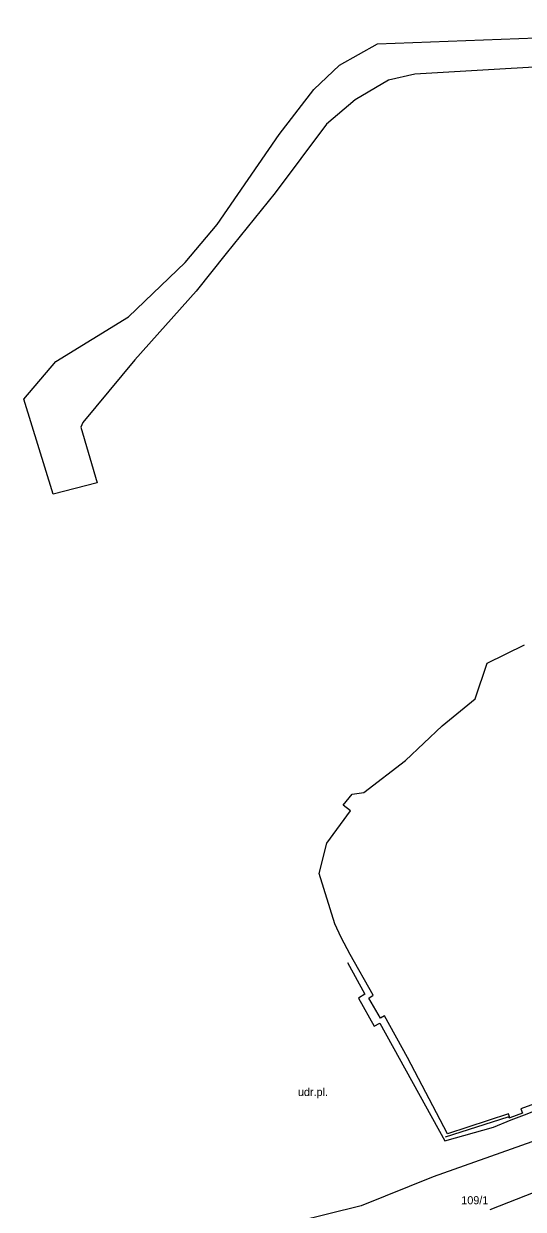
# Model space of a CAD drawing. Extents: x -836568 to -836015, y -1070547 to -1070212.
# Drawn here: x -836568.3 to -836522, y -1070322.1 to -1070212.1 of the extents above; entities that cross this region are included whole.
import ezdxf

# ---------------------------------------------------------------- set-up
doc = ezdxf.new("R2010")
doc.units = 0
for name, color, linetype in [('BodPole_mer', 7, 'Continuous'), ('Doprava_hranice', 7, 'Continuous'), ('OstPloch_hranice', 7, 'Continuous'), ('RuianPar_popis', 7, 'Continuous'), ('Stavby_linie', 7, 'Continuous'), ('Vodstvo_hranice', 7, 'Continuous'), ('Zelen_kody', 7, 'Continuous')]:
    doc.layers.add(name, color=color, linetype=linetype)

msp = doc.modelspace()

# ---------------------------------------------------------------- linework, layer by layer
at = {"layer": 'BodPole_mer'}
for p, q in [((-836536.32, -1070302.47), (-836536.32, -1070302.47)), ((-836535.91, -1070302.21), (-836535.91, -1070302.21)), ((-836534.86, -1070304.13), (-836534.86, -1070304.13)), ((-836535.82, -1070305.08), (-836535.82, -1070305.08)), ((-836535.28, -1070304.8), (-836535.28, -1070304.8)), ((-836535.22, -1070304.34), (-836535.22, -1070304.34)), ((-836532.73, -1070307.98), (-836532.73, -1070307.98)), ((-836522.22, -1070312.76), (-836522.22, -1070312.76)), ((-836523.38, -1070313.48), (-836523.38, -1070313.48)), ((-836523.35, -1070313.2), (-836523.35, -1070313.2)), ((-836523.23, -1070313.58), (-836523.23, -1070313.58)), ((-836523.12, -1070313.78), (-836523.12, -1070313.78)), ((-836522.07, -1070313.16), (-836522.07, -1070313.16)), ((-836529.02, -1070315.07), (-836529.02, -1070315.07)), ((-836524.75, -1070314.46), (-836524.75, -1070314.46)), ((-836529.27, -1070315.73), (-836529.27, -1070315.73)), ((-836529.2, -1070315.35), (-836529.2, -1070315.35)), ((-836530.36, -1070319.04), (-836530.36, -1070319.04)), ((-836537.03, -1070321.73), (-836537.03, -1070321.73))]:
    msp.add_line(p, q, dxfattribs=at)
at = {"layer": 'Doprava_hranice'}
for points in [[(-836565.55, -1070255.75), (-836568.29, -1070246.94), (-836565.3, -1070243.45), (-836558.59, -1070239.29), (-836553.32, -1070234.26), (-836550.36, -1070230.73), (-836544.63, -1070222.38), (-836541.42, -1070218.21), (-836539.02, -1070215.95), (-836535.5, -1070213.99), (-836517.48, -1070213.29), (-836497.22, -1070212.11), (-836494.05, -1070212.5), (-836489.39, -1070214.02), (-836485.93, -1070216.36), (-836482.28, -1070220.4), (-836478.23, -1070227.56), (-836471.79, -1070243.33), (-836465.92, -1070256.62), (-836463.85, -1070260.25), (-836463.13, -1070260.78)], [(-836466.54, -1070263.19), (-836474.56, -1070243.73), (-836478.12, -1070235.21), (-836483.33, -1070224.14), (-836486.58, -1070219.75), (-836489.27, -1070217.57), (-836492.22, -1070215.97), (-836495.08, -1070215.2), (-836498.82, -1070214.84), (-836513.64, -1070215.7), (-836532.05, -1070216.8), (-836534.5, -1070217.36), (-836537.57, -1070219.18), (-836540.24, -1070221.43), (-836545, -1070227.8), (-836549.52, -1070233.43), (-836552.32, -1070236.92), (-836557.98, -1070243.27), (-836562.8, -1070249.08), (-836563.01, -1070249.54), (-836561.48, -1070254.69), (-836565.55, -1070255.75)], [(-836486.39, -1070290.44), (-836494.37, -1070298.76), (-836499.1, -1070302.73), (-836502.92, -1070305.55), (-836506.93, -1070308.25), (-836509.27, -1070309.72), (-836512.75, -1070311.69), (-836519.45, -1070314.99), (-836521.21, -1070315.81), (-836530.36, -1070319.04)], [(-836525.05, -1070322.08), (-836520.89, -1070320.45), (-836511.44, -1070316.88), (-836510.57, -1070316.45), (-836509.63, -1070316.04), (-836508.64, -1070315.79), (-836507.63, -1070315.7), (-836506.6, -1070315.77), (-836505.63, -1070316.02), (-836504.69, -1070316.45), (-836503.83, -1070316.95), (-836503.04, -1070317.62), (-836502.41, -1070318.42), (-836501.96, -1070319.33), (-836501.67, -1070320.32), (-836501.58, -1070321.32), (-836501.69, -1070322.09), (-836502.08, -1070323), (-836503.14, -1070325.25), (-836503.34, -1070325.71), (-836503.44, -1070326.18), (-836504.04, -1070330.63), (-836504.64, -1070331.81)], [(-836530.36, -1070319.04), (-836537.03, -1070321.73), (-836555.38, -1070326.29), (-836561.14, -1070327.96), (-836562.04, -1070328.06)]]:
    msp.add_lwpolyline(points, dxfattribs=at)
at = {"layer": 'OstPloch_hranice'}
msp.add_line((-836523.38, -1070313.48), (-836523.23, -1070313.58), dxfattribs=at)
at = {"layer": 'RuianPar_popis'}
msp.add_line((-836527.74, -1070321.6), (-836527.74, -1070321.6), dxfattribs=at)
at = {"layer": 'Stavby_linie'}
msp.add_line((-836529.2, -1070315.35), (-836523.38, -1070313.48), dxfattribs=at)
at = {"layer": 'Vodstvo_hranice'}
for points in [[(-836520.29, -1070312.03), (-836522.22, -1070312.76), (-836522.07, -1070313.16), (-836523.23, -1070313.58), (-836523.35, -1070313.2), (-836529.02, -1070315.07), (-836532.73, -1070307.98), (-836534.86, -1070304.13), (-836535.22, -1070304.34), (-836536.32, -1070302.47), (-836535.91, -1070302.21), (-836538.03, -1070298.42), (-836538.87, -1070296.86), (-836539.46, -1070295.59), (-836540.9, -1070290.92), (-836540.19, -1070288.1), (-836538.02, -1070285.12), (-836538.7, -1070284.57), (-836537.84, -1070283.58), (-836536.78, -1070283.42), (-836532.91, -1070280.44), (-836529.5, -1070277.24), (-836526.44, -1070274.72), (-836525.34, -1070271.43), (-836521.88, -1070269.71)], [(-836538.28, -1070299.17), (-836536.67, -1070302.12), (-836537.27, -1070302.49), (-836535.82, -1070305.08), (-836535.28, -1070304.8), (-836529.27, -1070315.73), (-836524.75, -1070314.46), (-836523.12, -1070313.78), (-836521.89, -1070313.32), (-836519.48, -1070312.36), (-836516.81, -1070310.51), (-836511.44, -1070307.01), (-836506.56, -1070303.42), (-836500.78, -1070297.61), (-836491.56, -1070288.65), (-836487.98, -1070285.34), (-836486.83, -1070284.4), (-836486.48, -1070284.32), (-836486.34, -1070284.49), (-836485.89, -1070284.09), (-836486.21, -1070283.75)]]:
    msp.add_lwpolyline(points, dxfattribs=at)

# ---------------------------------------------------------------- texts
at = {"layer": 'RuianPar_popis'}
msp.add_text('109/1', height=0.75, dxfattribs=at).set_placement((-836527.74, -1070321.6))
at = {"layer": 'Zelen_kody'}
msp.add_text('udr.pl.', height=0.75, dxfattribs=at).set_placement((-836542.88, -1070311.56))

doc.saveas('drawing.dxf')
